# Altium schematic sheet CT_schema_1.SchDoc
size 570 x 539 mm
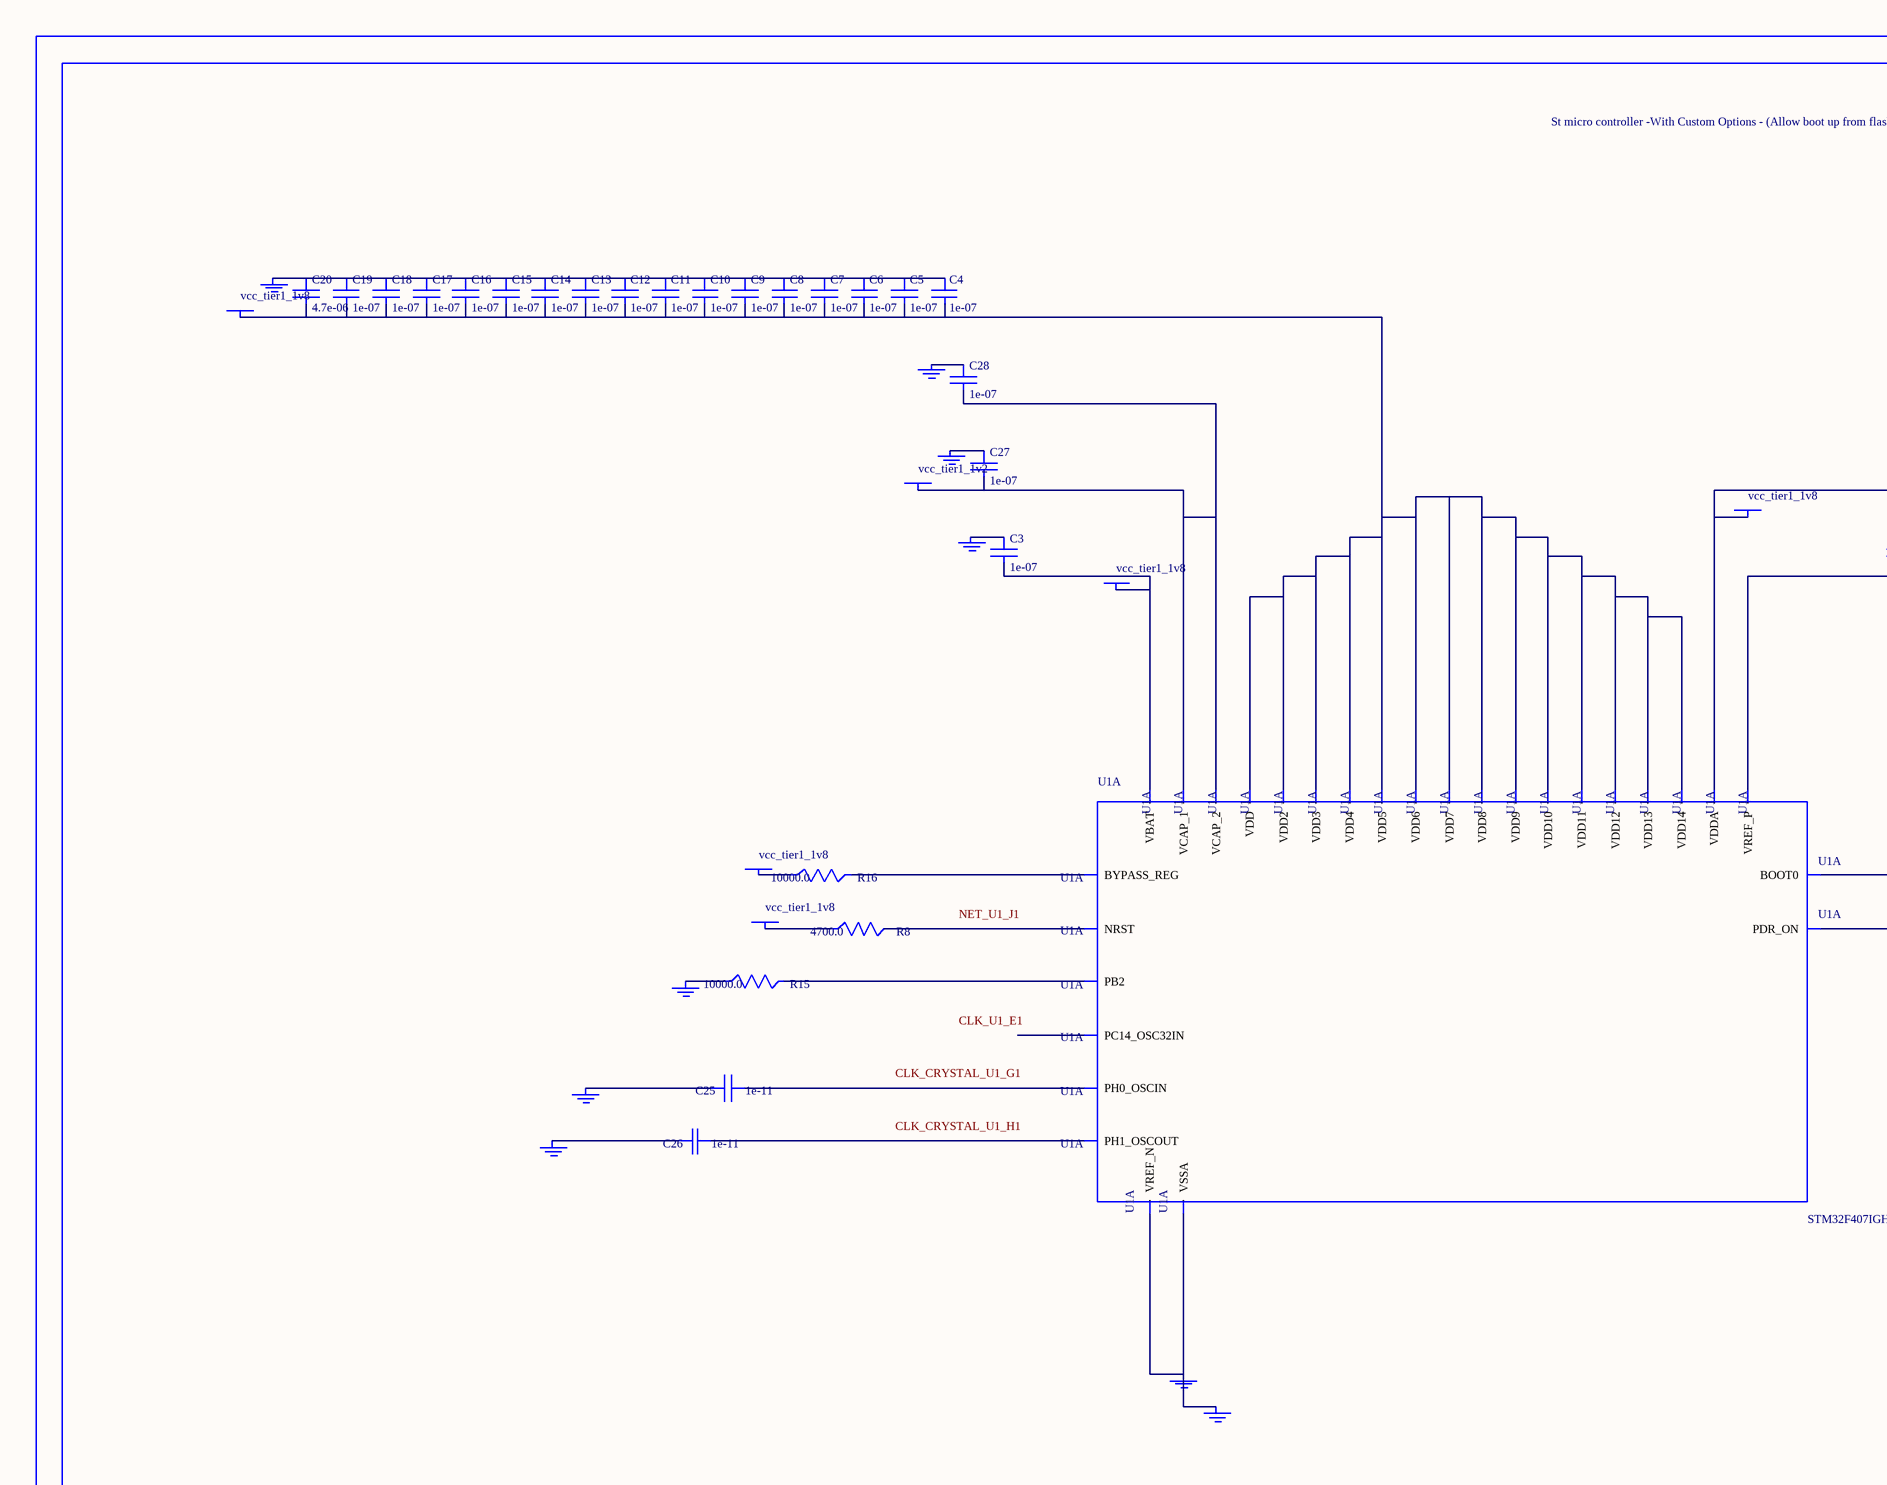
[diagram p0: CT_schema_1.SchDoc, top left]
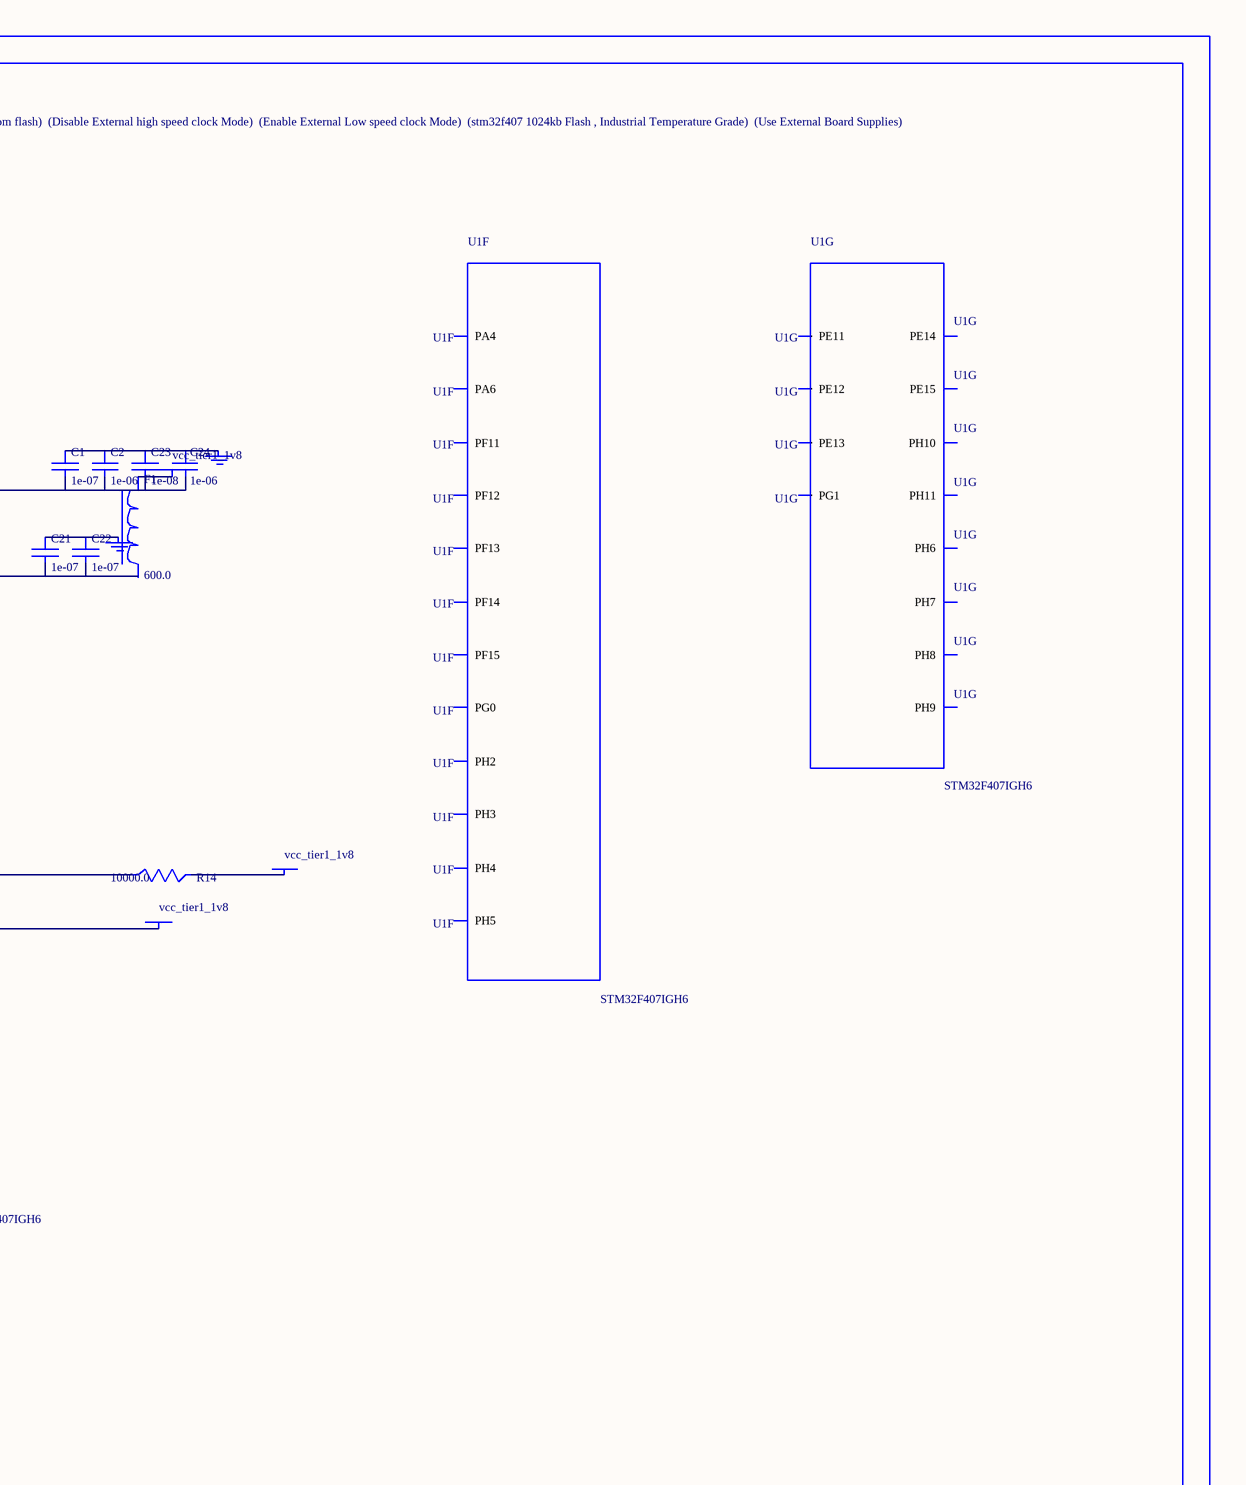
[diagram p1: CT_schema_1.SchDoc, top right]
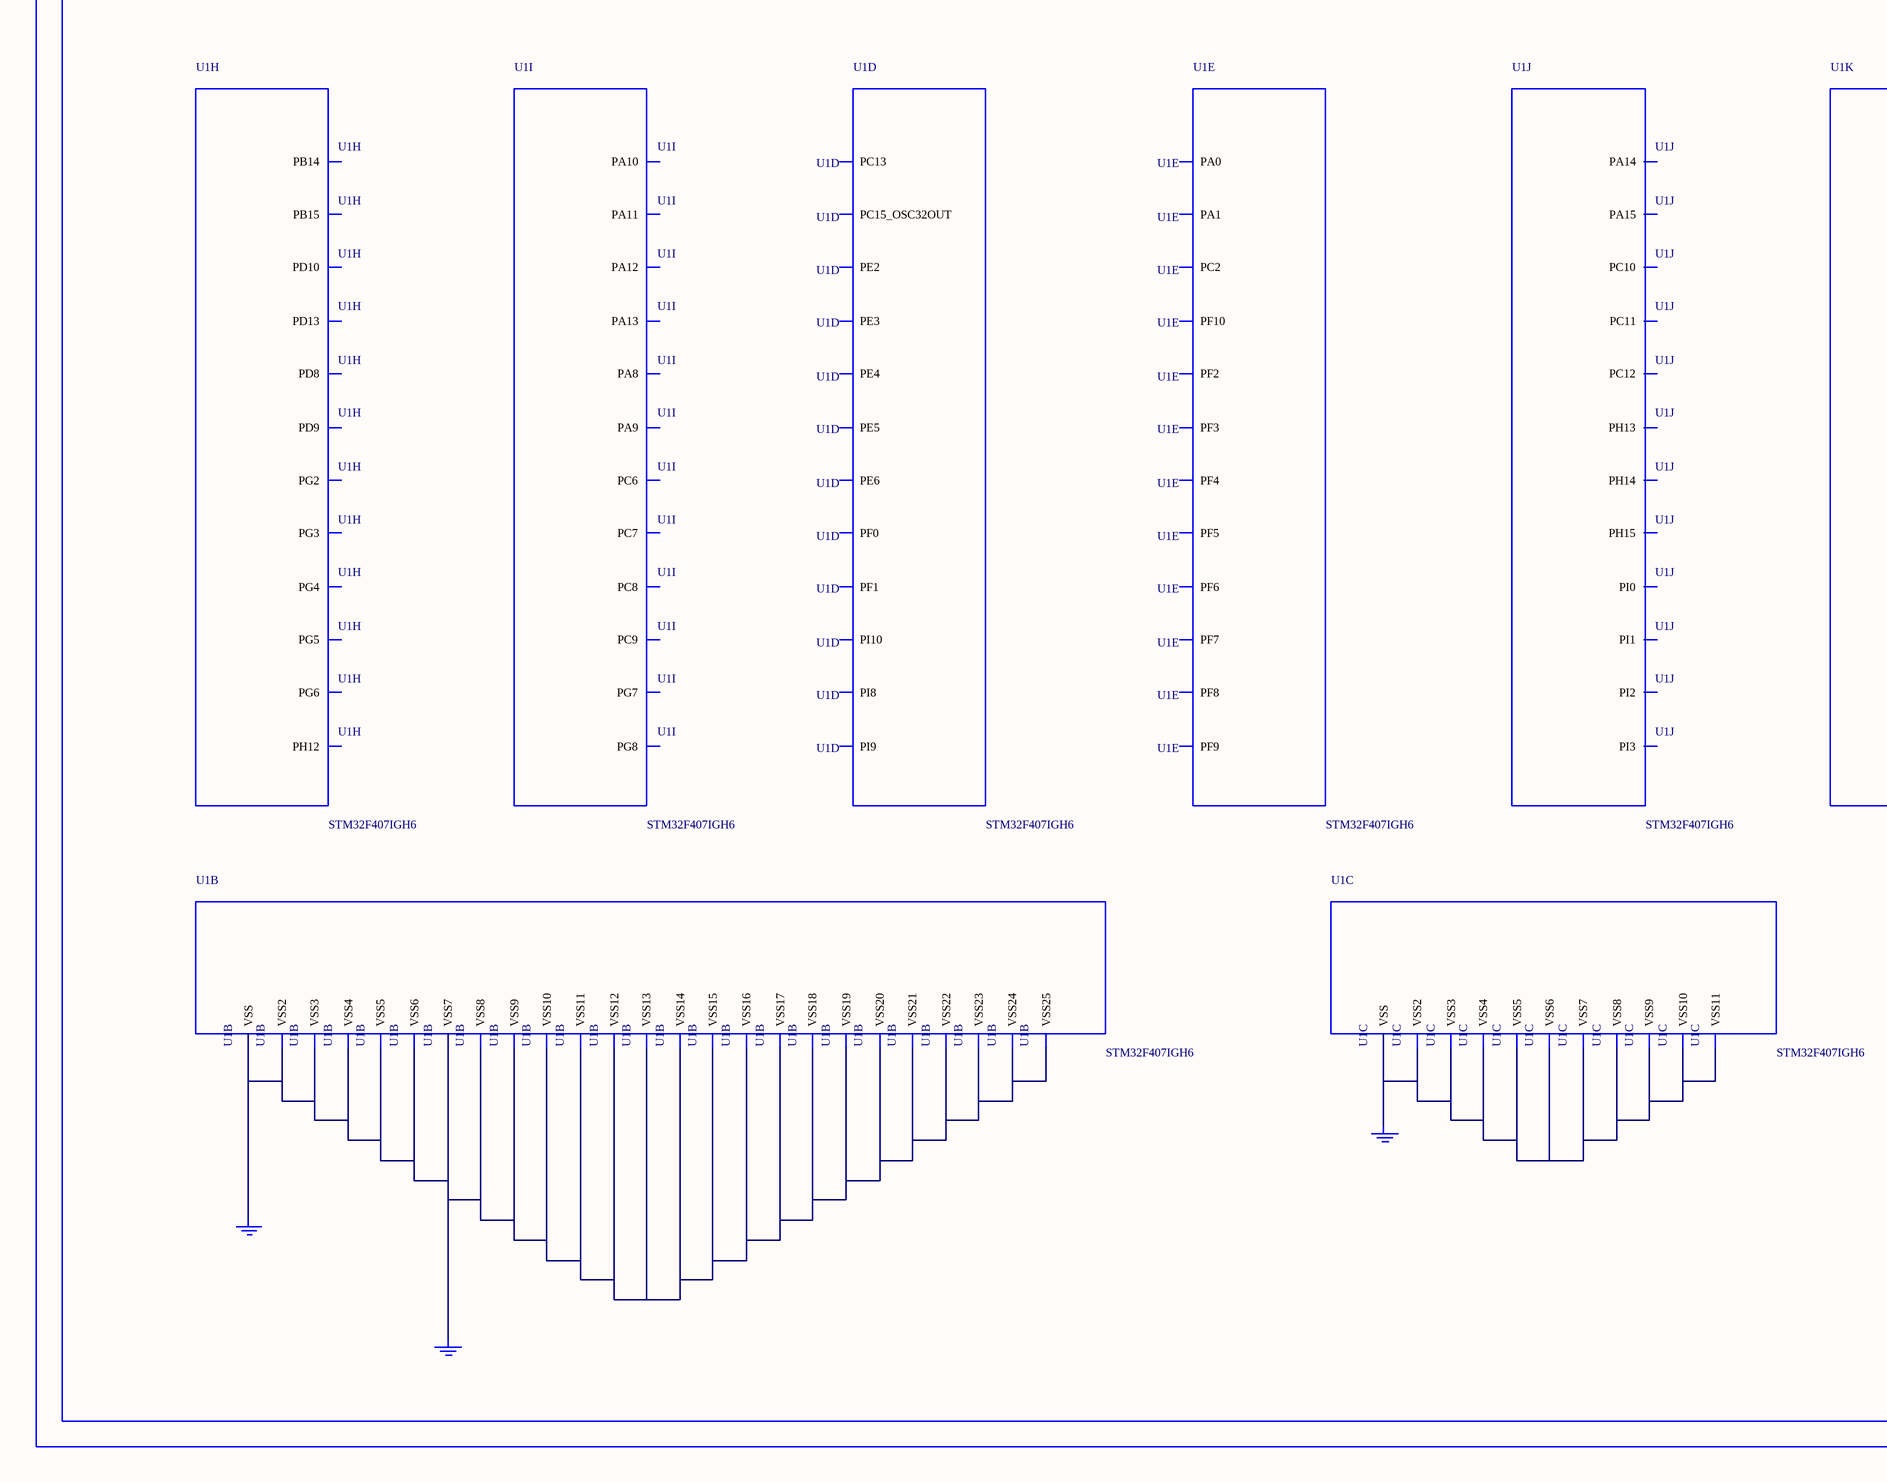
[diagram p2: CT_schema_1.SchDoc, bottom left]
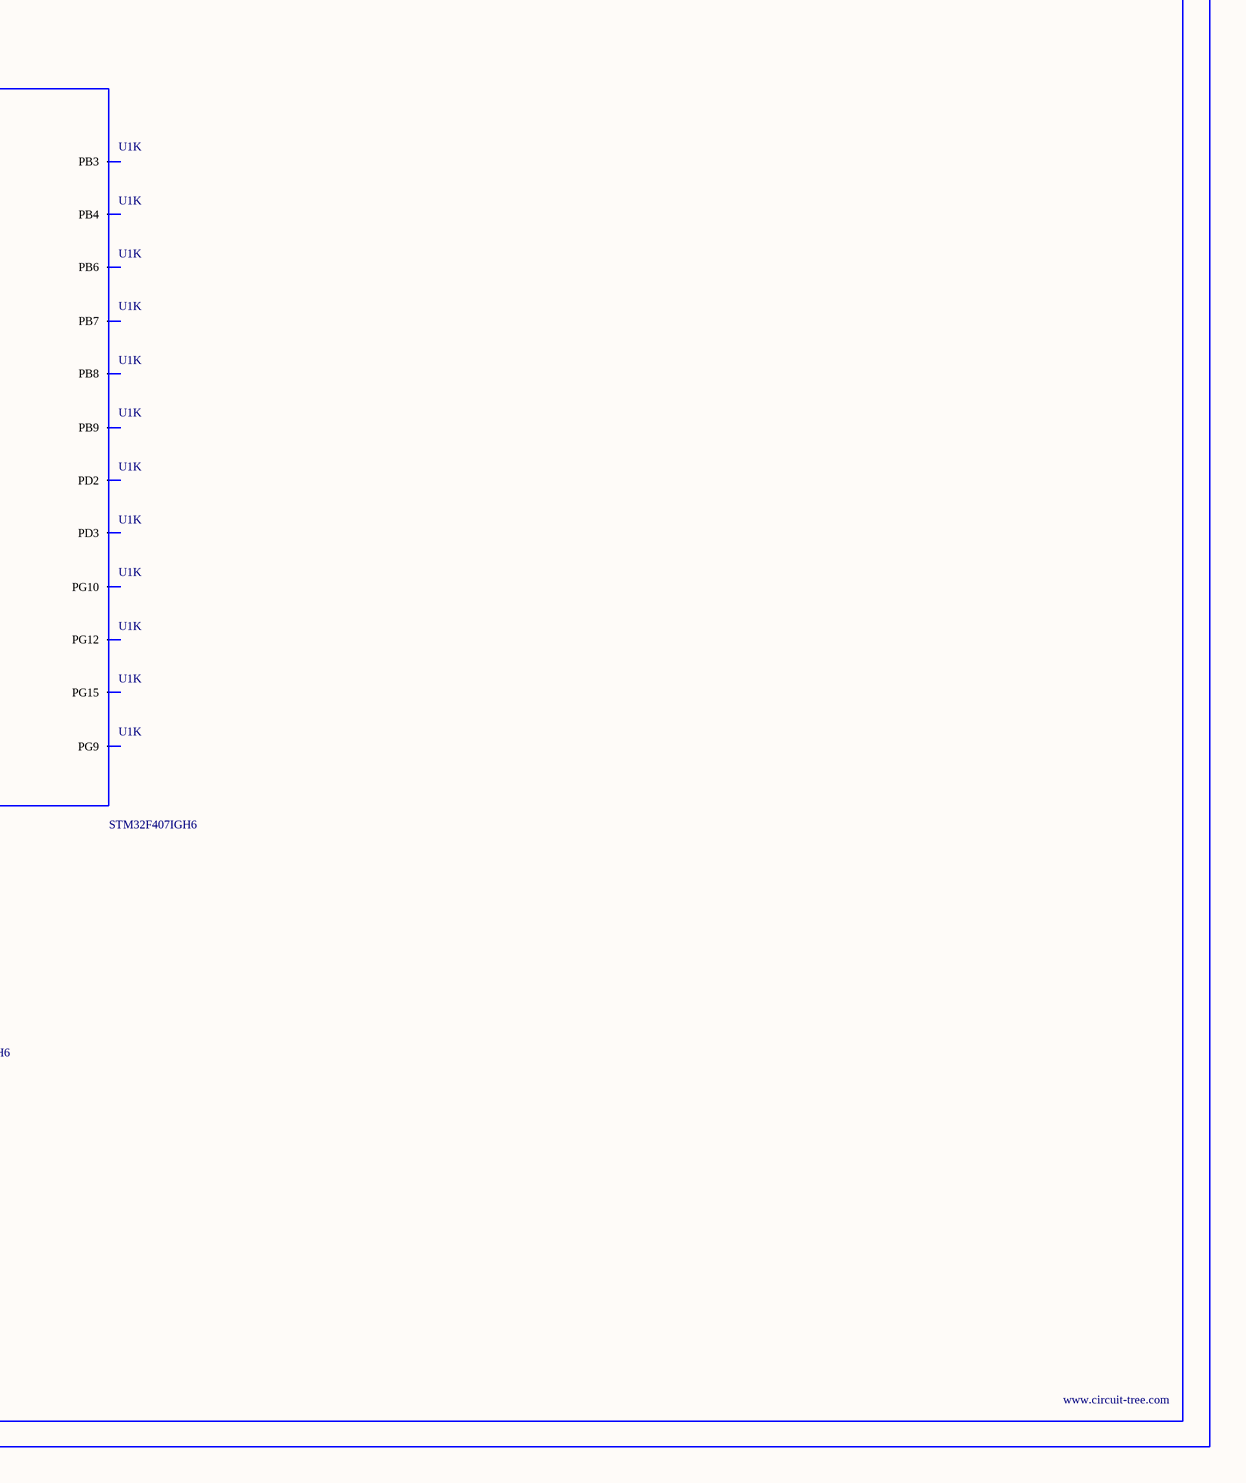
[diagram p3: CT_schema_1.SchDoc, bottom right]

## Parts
BORDER0  (no value)
C1  1e-07  [C0402]
C2  1e-06  [C0603]
C3  1e-07  [C0402]
C4  1e-07  [C0402]
C5  1e-07  [C0402]
C6  1e-07  [C0402]
C7  1e-07  [C0402]
C8  1e-07  [C0402]
C9  1e-07  [C0402]
C10  1e-07  [C0402]
C11  1e-07  [C0402]
C12  1e-07  [C0402]
C13  1e-07  [C0402]
C14  1e-07  [C0402]
C15  1e-07  [C0402]
C16  1e-07  [C0402]
C17  1e-07  [C0402]
C18  1e-07  [C0402]
C19  1e-07  [C0402]
C20  4.7e-06  [C0805]
C21  1e-07  [C0402]
C22  1e-07  [C0402]
C23  1e-08  [C0603]
C24  1e-06  [C0603]
C25  1e-11  [C0402]
C26  1e-11  [C0402]
C27  1e-07  [C0402]
C28  1e-07  [C0402]
F1  600.0  [L0603]
GND_INSTANCE_0_0  (no value)
GND_INSTANCE_0_1  (no value)
GND_INSTANCE_0_2  (no value)
GND_INSTANCE_0_3  (no value)
GND_INSTANCE_0_4  (no value)
GND_INSTANCE_0_5  (no value)
GND_INSTANCE_0_6  (no value)
GND_INSTANCE_0_7  (no value)
GND_INSTANCE_0_8  (no value)
GND_INSTANCE_0_9  (no value)
GND_INSTANCE_0_10  (no value)
GND_INSTANCE_0_11  (no value)
GND_INSTANCE_0_12  (no value)
GND_INSTANCE_0_13  (no value)
POWER_INSTANCE_0_0  vcc_tier1_1v8
POWER_INSTANCE_0_1  vcc_tier1_1v8
POWER_INSTANCE_0_2  vcc_tier1_1v8
POWER_INSTANCE_0_3  vcc_tier1_1v8
POWER_INSTANCE_0_4  vcc_tier1_1v8
POWER_INSTANCE_0_5  vcc_tier1_1v8
POWER_INSTANCE_0_6  vcc_tier1_1v2
POWER_INSTANCE_0_7  vcc_tier1_1v8
POWER_INSTANCE_0_8  vcc_tier1_1v8
R8  4700.0  [R0603]
R14  10000.0  [R0603]
R15  10000.0  [R0603]
R16  10000.0  [R0603]
U1  STM32F407IGH6  [UFBGA176]  (parts A,B,C,D,E,F,G,H,I,J,K of 15)

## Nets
NetC1_1: C1.1 C2.1 C23.1 C24.1 GND_INSTANCE_0_0.0(GND)
NetC1_2: C1.2 C2.2 C23.2 C24.2 F1.1 POWER_INSTANCE_0_0.0(PWR) POWER_INSTANCE_0_3.0(PWR) U1.R1(VDDA)
NetC3_1: C3.1 GND_INSTANCE_0_1.0(GND)
NetC3_2: C3.2 POWER_INSTANCE_0_1.0(PWR) U1.C1(VBAT)
NetC4_1: C4.1 C5.1 C6.1 C7.1 C8.1 C9.1 C10.1 C11.1 C12.1 C13.1 C14.1 C15.1 C16.1 C17.1 C18.1 C19.1 C20.1 GND_INSTANCE_0_2.0(GND)
NetC4_2: C4.2 C5.2 C6.2 C7.2 C8.2 C9.2 C10.2 C11.2 C12.2 C13.2 C14.2 C15.2 C16.2 C17.2 C18.2 C19.2 C20.2 POWER_INSTANCE_0_2.0(PWR) U1.C5(VDD) U1.C7(VDD2) U1.C8(VDD3) U1.C9(VDD4) U1.F3(VDD5) U1.G3(VDD7) U1.G13(VDD6) U1.H13(VDD8) U1.J12(VDD9) U1.J13(VDD10) U1.K4(VDD11) U1.N8(VDD13) U1.N9(VDD14) U1.N10(VDD12)
NetC21_1: C21.1 C22.1 GND_INSTANCE_0_3.0(GND)
NetC21_2: C21.2 C22.2 U1.P1(VREF_P)
NetC25_1: C25.1 U1.G1(PH0_OSCIN)
NetC25_2: C25.2 GND_INSTANCE_0_4.0(GND)
NetC26_1: C26.1 U1.H1(PH1_OSCOUT)
NetC26_2: C26.2 GND_INSTANCE_0_5.0(GND)
NetC27_1: C27.1 GND_INSTANCE_0_7.0(GND)
NetC27_2: C27.2 C28.2 POWER_INSTANCE_0_6.0(PWR) U1.F13(VCAP_2) U1.M10(VCAP_1)
NetC28_1: C28.1 GND_INSTANCE_0_8.0(GND)
NetGND_INSTANCE_0_6_0: GND_INSTANCE_0_6.0(GND) R15.1
NetGND_INSTANCE_0_9_0: GND_INSTANCE_0_9.0(GND) GND_INSTANCE_0_10.0(GND) U1.M1(VSSA) U1.N1(VREF_N)
NetGND_INSTANCE_0_11_0: GND_INSTANCE_0_11.0(GND) GND_INSTANCE_0_12.0(GND) U1.D5(VSS) U1.D7(VSS2) U1.D8(VSS3) U1.D9(VSS4) U1.F2(VSS7) U1.F6(VSS8) U1.F7(VSS9) U1.F8(VSS10) U1.F9(VSS11) U1.F10(VSS5) U1.F12(VSS6) U1.G2(VSS14) U1.G6(VSS15) U1.G7(VSS16) U1.G8(VSS17) U1.G9(VSS18) U1.G10(VSS12) U1.G12(VSS13) U1.H6(VSS21) U1.H7(VSS22) U1.H8(VSS23) U1.H9(VSS24) U1.H10(VSS19) U1.H12(VSS20) U1.J10(VSS25)
NetGND_INSTANCE_0_13_0: GND_INSTANCE_0_13.0(GND) U1.J6(VSS) U1.J7(VSS2) U1.J8(VSS3) U1.J9(VSS4) U1.K6(VSS6) U1.K7(VSS7) U1.K8(VSS8) U1.K9(VSS9) U1.K10(VSS5) U1.M8(VSS10) U1.M9(VSS11)
NetPOWER_INSTANCE_0_4_0: POWER_INSTANCE_0_4.0(PWR) R14.2
NetPOWER_INSTANCE_0_5_0: POWER_INSTANCE_0_5.0(PWR) R16.1
NetPOWER_INSTANCE_0_7_0: POWER_INSTANCE_0_7.0(PWR) U1.C6(PDR_ON)
NetPOWER_INSTANCE_0_8_0: POWER_INSTANCE_0_8.0(PWR) R8.1
NetR8_2: R8.2 U1.J1(NRST)
NetR14_1: R14.1 U1.D6(BOOT0)
NetR15_2: R15.2 U1.M6(PB2)
NetR16_2: R16.2 U1.L4(BYPASS_REG)

Not connected (* = marked no-connect by the designer): F1 2; U1 A1(PE3) A2(PE2) A5(PB8) A9(PB4) A10(PB3) A12(PC12) A13(PA15) A14(PA14) A15(PA13) B1(PE4) B2(PE5) B3(PE6) B4(PB9) B5(PB7) B6(PB6) B7(PG15) B8(PG12) B10(PG10) B13(PC11) B14(PC10) B15(PA12) C10(PG9) C13(PI3) C14(PI2) C15(PA11) D1(PC13) D2(PI8) D3(PI9) D11(PD3) D12(PD2) D13(PH15) D14(PI1) D15(PA10) E1(PC14_OSC32IN) E2(PF0) E3(PI10) E12(PH13) E13(PH14) E14(PI0) E15(PA9) F1(PC15_OSC32OUT) F4(PH2) F14(PC9) F15(PA8) G4(PH3) G14(PC8) G15(PC7) H2(PF2) H3(PF1) H4(PH4) H14(PG8) H15(PC6) J2(PF3) J3(PF4) J4(PH5) J14(PG7) J15(PG6) K1(PF7) K2(PF6) K3(PF5) K12(PH12) K13(PG5) K14(PG4) K15(PG3) L1(PF10) L2(PF9) L3(PF8) L12(PH11) L13(PH10) L15(PG2) M4(PC2) M7(PG1) M11(PH6) M12(PH8) M13(PH9) M15(PD13) N2(PA1) N3(PA0) N4(PA4) N6(PF13) N7(PG0) N11(PE13) N12(PH7) N15(PD10) P3(PA6) P6(PF12) P7(PF15) P10(PE11) P11(PE14) P14(PD9) P15(PD8) R6(PF11) R7(PF14) R10(PE12) R11(PE15) R14(PB14) R15(PB15)

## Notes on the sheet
- Labels drawn without touching a wire or pin: CLK_CRYSTAL_U1_G1, CLK_CRYSTAL_U1_H1, CLK_U1_E1, NET_U1_J1

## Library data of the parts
BORDER0 = BORDER_PAGE0
C1 C3-C19 C21 C22 C27 C28 = C0402C104K3RACTU
C2 C24 = C0603C105K3RACTU
C20 = C0805C475K4RACTU
C23 = 06035C103K4Z2A
C25 C26 = C0402C100K3GACTU
F1 = Z0603C601ASMST
GND_INSTANCE_0_0-GND_INSTANCE_0_13 = GND
POWER_INSTANCE_0_0-POWER_INSTANCE_0_8 = PWR
R8 = RC0603JR-074K7L
R14-R16 = RC0603JR-0710KL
